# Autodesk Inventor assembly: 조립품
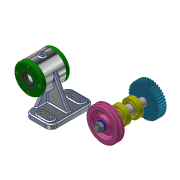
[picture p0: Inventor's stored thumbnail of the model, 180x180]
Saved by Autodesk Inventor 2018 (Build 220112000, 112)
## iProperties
Created: 2023-08
Part Number: 조립품
Material: 일반
Document SubType Name: Assembly
Designer: home
Author: home
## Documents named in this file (12)
- C:\Users\home\Desktop\730806V1011\조립품.iam
- C:\Users\home\Desktop\730806V1011\본체.ipt
- C:\Users\home\Desktop\730806V1011\V벨트풀리.ipt
- C:\Users\home\Desktop\730806V1011\너트 M12x1.25.ipt
- C:\Users\home\Desktop\730806V1011\베어링 6204.ipt
- C:\Users\home\Desktop\730806V1011\볼트 M4 x 12.ipt
- C:\Users\home\Desktop\730806V1011\스퍼기어.ipt
- C:\Users\home\Desktop\730806V1011\오일실 20x35x8.ipt
- C:\Users\home\Desktop\730806V1011\와셔 12x24.ipt
- C:\Users\home\Desktop\730806V1011\축.ipt
- C:\Users\home\Desktop\730806V1011\커버.ipt
- C:\Users\home\Desktop\730806V1011\키 5x5.ipt
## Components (1 placed, 1 different names)
1. V벨트풀리:1
